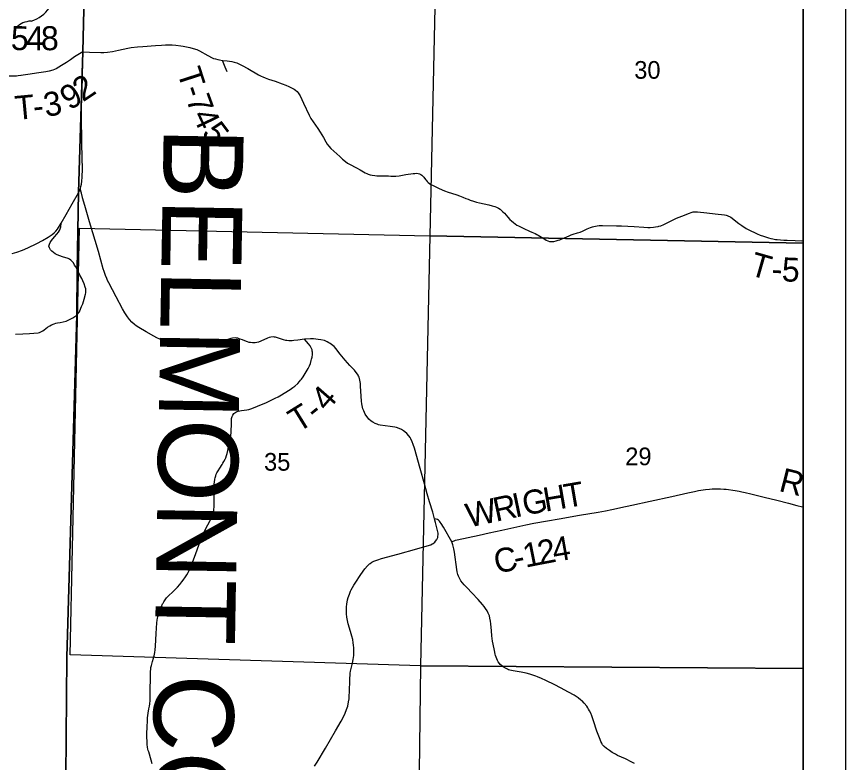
# Model space of a CAD drawing. Extents: x 0 to 34, y 0 to 22.
# Drawn here: x 7.038 to 9, y 17.164 to 18.929 of the extents above; entities that cross this region are included whole.
import ezdxf

# ---------------------------------------------------------------- set-up
doc = ezdxf.new("R2010")
doc.units = 0
for name, color, linetype in [('GM_X_Corporation', 7, 'Continuous'), ('GM_X_County_Road', 7, 'Continuous'), ('GM_X_County_Road_Text', 7, 'Continuous'), ('GM_X_County_Text', 7, 'Continuous'), ('GM_X_Section_Text', 7, 'Continuous'), ('GM_X_State_Route', 7, 'Continuous'), ('GM_X_State_Shield', 7, 'Continuous'), ('GM_X_Township_Road', 7, 'Continuous'), ('GM_X_Township_Road_Text', 7, 'Continuous'), ('GM_X_Township_Text', 7, 'Continuous'), ('SH_Data', 7, 'Continuous')]:
    doc.layers.add(name, color=color, linetype=linetype)

msp = doc.modelspace()

# ---------------------------------------------------------------- linework, layer by layer
at = {"layer": 'GM_X_Corporation'}
for points in [[(7.1227, 14.1), (8.9, 14.1), (8.9, 20.9), (7.231, 20.9), (7.2244, 20.2649), (7.1982, 19.2496), (7.1981, 19.2461), (7.1974, 19.2018), (7.1957, 19.0991), (7.1992, 18.9556), (7.197, 18.9465), (7.1949, 18.8464), (7.1846, 18.5133), (7.1817, 18.3306), (7.1804, 18.2238), (7.1572, 17.4131), (7.1504, 16.6562), (7.1434, 16.3848), (7.1318, 15.4937)], [(8.9, 18.393), (8.9, 19.2258), (8.0347, 19.2404), (8.0161, 18.4109)], [(8.0161, 18.4109), (7.9945, 17.3927), (7.1652, 17.4189), (7.1866, 18.4288)], [(8.9, 17.3865), (8.9, 18.393), (8.0161, 18.4109), (7.9945, 17.3927)], [(8.9, 16.3711), (8.9, 17.3865), (7.9945, 17.3927), (7.9815, 16.3875)]]:
    msp.add_lwpolyline(points, close=True, dxfattribs=at)
at = {"layer": 'GM_X_County_Road'}
for points in [[(8.068, 17.6868), (8.0768, 17.69), (8.0809, 17.6912), (8.133, 17.7023), (8.1569, 17.7076), (8.1864, 17.7138), (8.2435, 17.7264), (8.2626, 17.7302), (8.2947, 17.736), (8.3222, 17.7408), (8.3703, 17.7492), (8.4148, 17.7567), (8.4319, 17.7597), (8.4469, 17.7627), (8.4578, 17.765), (8.4687, 17.7674), (8.4943, 17.7732), (8.5376, 17.7827), (8.5892, 17.7935), (8.6269, 17.8022), (8.6427, 17.8058), (8.6524, 17.8077), (8.6633, 17.8094), (8.6684, 17.81), (8.6783, 17.8113), (8.6844, 17.8118), (8.6911, 17.8121), (8.7043, 17.812), (8.7122, 17.8114), (8.718, 17.8108), (8.7389, 17.8079), (8.7481, 17.8063), (8.7546, 17.8051), (8.7628, 17.8034), (8.7758, 17.8003), (8.8077, 17.7922), (8.8373, 17.7847), (8.8649, 17.7777), (8.8848, 17.7727), (8.8982, 17.7695), (8.9, 17.7691)], [(8.068, 17.6868), (8.0482, 17.7214), (8.0429, 17.7297), (8.041, 17.7328), (8.0388, 17.7355), (8.0368, 17.7374), (8.0342, 17.7392), (8.031, 17.7404), (8.0276, 17.741)], [(8.501, 17.1615), (8.4942, 17.1652), (8.4791, 17.1725), (8.4605, 17.1811), (8.458, 17.1824), (8.4554, 17.1838), (8.4482, 17.188), (8.4412, 17.1926), (8.4345, 17.1974), (8.4286, 17.2023), (8.4269, 17.2041), (8.4252, 17.2063), (8.4242, 17.2078), (8.423, 17.2098), (8.4211, 17.2139), (8.4194, 17.2185), (8.4119, 17.2382), (8.404, 17.2631), (8.3996, 17.2749), (8.3971, 17.281), (8.3944, 17.2867), (8.3921, 17.2907), (8.3904, 17.2934), (8.3877, 17.2973), (8.3817, 17.3049), (8.3765, 17.3098), (8.374, 17.312), (8.3676, 17.3169), (8.3577, 17.3233), (8.3447, 17.3308), (8.3259, 17.3409), (8.3118, 17.3482), (8.291, 17.3582), (8.2802, 17.3632), (8.2713, 17.3671), (8.2674, 17.3686), (8.2597, 17.3712), (8.2531, 17.3732), (8.2446, 17.3753), (8.2324, 17.3776), (8.2133, 17.381), (8.2097, 17.3817), (8.2057, 17.3827), (8.2026, 17.3838), (8.2, 17.3849), (8.1968, 17.3865), (8.1923, 17.389), (8.189, 17.3911), (8.185, 17.3942), (8.183, 17.3961), (8.1808, 17.3988), (8.1783, 17.4025), (8.1765, 17.4058), (8.1748, 17.4092), (8.1732, 17.4133), (8.1718, 17.4175), (8.171, 17.4204), (8.1691, 17.429), (8.166, 17.4441), (8.1649, 17.4514), (8.1633, 17.4641), (8.1621, 17.4756), (8.1606, 17.492), (8.1597, 17.4989), (8.1585, 17.5058), (8.1573, 17.5109), (8.1568, 17.5126), (8.1545, 17.5178), (8.1516, 17.5233), (8.1483, 17.5286), (8.1447, 17.5335), (8.1407, 17.5383), (8.1303, 17.5502), (8.127, 17.5536), (8.1194, 17.5618), (8.1006, 17.5813), (8.0975, 17.5847), (8.0936, 17.5894), (8.09, 17.5944), (8.0879, 17.5976), (8.0856, 17.6019), (8.0841, 17.6053), (8.0829, 17.6088), (8.0818, 17.6124), (8.0812, 17.6152), (8.0803, 17.6208), (8.0748, 17.6618), (8.0732, 17.67), (8.071, 17.6791), (8.0693, 17.6841), (8.068, 17.6868)]]:
    msp.add_lwpolyline(points, dxfattribs=at)
at = {"layer": 'GM_X_State_Route'}
for points in [[(7.1848, 18.5127), (7.1876, 18.5185), (7.189, 18.5224), (7.1902, 18.5276), (7.1914, 18.5332), (7.1923, 18.5399), (7.1932, 18.5491), (7.1935, 18.555), (7.1941, 18.5639), (7.1939, 18.5763), (7.1933, 18.5881), (7.1929, 18.6), (7.1927, 18.6262), (7.1926, 18.6491), (7.192, 18.6745), (7.1918, 18.6871), (7.192, 18.7145), (7.1935, 18.7555), (7.1941, 18.7873), (7.1949, 18.8249), (7.1951, 18.8459), (7.1953, 18.8628), (7.1956, 18.8765), (7.1961, 18.9023), (7.1966, 18.921), (7.1971, 18.9313)], [(7.7436, 17.1553), (7.7493, 17.165), (7.7691, 17.1984), (7.7812, 17.2189), (7.793, 17.2388), (7.806, 17.2619), (7.8108, 17.2708), (7.8157, 17.2809), (7.8191, 17.2894), (7.8219, 17.2977), (7.8239, 17.3075), (7.8249, 17.315), (7.8256, 17.3225), (7.8258, 17.3304), (7.826, 17.3364), (7.8265, 17.3548), (7.8268, 17.3638), (7.8273, 17.3711), (7.8279, 17.3759), (7.8287, 17.3801), (7.8332, 17.3994), (7.8349, 17.408), (7.8362, 17.4178), (7.8365, 17.4232), (7.8366, 17.4291), (7.8364, 17.4353), (7.8358, 17.4415), (7.835, 17.4477), (7.8336, 17.4549), (7.8317, 17.4628), (7.8282, 17.4746), (7.8233, 17.4925), (7.8214, 17.5002), (7.8199, 17.508), (7.819, 17.5159), (7.8186, 17.5242), (7.8188, 17.5316), (7.8197, 17.5394), (7.8204, 17.5437), (7.8216, 17.5491), (7.8233, 17.555), (7.8246, 17.559), (7.826, 17.5629), (7.8286, 17.5693), (7.8301, 17.5726), (7.8329, 17.5781), (7.8361, 17.5836), (7.8394, 17.5889), (7.8532, 17.6093), (7.8626, 17.6225), (7.8689, 17.6298), (7.8735, 17.6341), (7.8753, 17.6355), (7.8791, 17.638), (7.8835, 17.6403), (7.8883, 17.6425), (7.8933, 17.6442), (7.9018, 17.6467), (7.9403, 17.6573), (7.9851, 17.6697), (8.0157, 17.6788), (8.0184, 17.6797), (8.0217, 17.6813), (8.024, 17.6827), (8.0283, 17.686), (8.0322, 17.6908), (8.0331, 17.6923), (8.0343, 17.6949), (8.0349, 17.6967), (8.0355, 17.6994), (8.0359, 17.7039), (8.0358, 17.7069), (8.0353, 17.7104), (8.0297, 17.7318), (8.0276, 17.741), (8.023, 17.7565), (8.0158, 17.7811), (8.0103, 17.8), (8.0037, 17.8238), (7.9932, 17.8603), (7.9796, 17.9079), (7.9769, 17.9169), (7.9744, 17.9234), (7.9714, 17.9299), (7.9693, 17.9332), (7.9667, 17.9369), (7.9615, 17.9431), (7.9571, 17.9469), (7.9539, 17.9493), (7.9488, 17.9525), (7.9435, 17.955), (7.9376, 17.957), (7.9336, 17.958), (7.9225, 17.9597), (7.899, 17.9626), (7.8947, 17.9636), (7.8916, 17.9646), (7.8865, 17.9667), (7.8814, 17.9696), (7.8774, 17.9723), (7.8719, 17.977), (7.8677, 17.982), (7.865, 17.9858), (7.8632, 17.9888), (7.8613, 17.9924), (7.8597, 17.9961), (7.858, 18.0009), (7.8567, 18.0052), (7.8559, 18.0087), (7.8551, 18.0131), (7.8544, 18.0193), (7.8525, 18.0548), (7.8518, 18.0614), (7.8508, 18.0693), (7.8499, 18.0729), (7.8487, 18.0762), (7.8476, 18.0785), (7.8464, 18.0808), (7.8449, 18.0831), (7.8417, 18.0875), (7.8376, 18.0925), (7.8268, 18.1041), (7.8155, 18.1167), (7.8042, 18.1304), (7.7988, 18.1373), (7.7944, 18.1433), (7.7897, 18.1485), (7.7836, 18.1535), (7.7807, 18.1556), (7.7775, 18.1577), (7.7736, 18.1598), (7.7667, 18.1625), (7.7579, 18.1645), (7.7519, 18.1656), (7.7466, 18.1663), (7.7412, 18.1668), (7.7336, 18.1672), (7.7192, 18.1664), (7.704, 18.164), (7.6943, 18.1625), (7.6904, 18.1621), (7.6878, 18.162), (7.6825, 18.1621), (7.6778, 18.1627), (7.6752, 18.1631), (7.6699, 18.1644), (7.6558, 18.1695), (7.651, 18.1707), (7.6482, 18.1711), (7.6462, 18.1712), (7.6401, 18.1708), (7.6362, 18.1699), (7.6317, 18.1681), (7.616, 18.1612), (7.6107, 18.1593), (7.6064, 18.1582), (7.6031, 18.1577), (7.5997, 18.1574), (7.5963, 18.1573), (7.5915, 18.1579), (7.5885, 18.1585), (7.585, 18.1595), (7.5787, 18.1617), (7.5725, 18.1642), (7.5674, 18.1664), (7.5635, 18.1677), (7.5614, 18.1682), (7.5583, 18.1687), (7.5559, 18.1689), (7.5488, 18.1685), (7.5448, 18.1676), (7.5147, 18.1575), (7.511, 18.1564), (7.5054, 18.1547), (7.496, 18.1524), (7.4881, 18.1509), (7.4833, 18.1501), (7.476, 18.1491), (7.4625, 18.1479), (7.4542, 18.1477), (7.4447, 18.1479), (7.4374, 18.1484), (7.4312, 18.1491), (7.4245, 18.1503), (7.417, 18.1519), (7.4102, 18.1537), (7.4024, 18.156), (7.3949, 18.1585), (7.3847, 18.1625), (7.3773, 18.1657), (7.37, 18.1692), (7.3629, 18.1729), (7.3448, 18.1833), (7.3274, 18.1934), (7.3208, 18.1978), (7.3168, 18.201), (7.3111, 18.2061), (7.305, 18.2129), (7.3003, 18.2192), (7.294, 18.2285), (7.2886, 18.2379), (7.2736, 18.2662), (7.2563, 18.2992), (7.2534, 18.3052), (7.2513, 18.3098), (7.2485, 18.3167), (7.2452, 18.3258), (7.243, 18.3327), (7.2316, 18.3732), (7.2108, 18.4435), (7.1998, 18.4823), (7.1941, 18.5006), (7.194, 18.5009), (7.1913, 18.5113), (7.19, 18.5164), (7.189, 18.5224)], [(7.0274, 18.3686), (7.0386, 18.3719), (7.0524, 18.3768), (7.0645, 18.3818), (7.0863, 18.3926), (7.0997, 18.3997), (7.1124, 18.4072), (7.1223, 18.4141), (7.1268, 18.4176), (7.131, 18.4219), (7.1351, 18.4267), (7.1439, 18.4404), (7.1551, 18.4614), (7.1693, 18.4864), (7.1848, 18.5127)]]:
    msp.add_lwpolyline(points, dxfattribs=at)
at = {"layer": 'GM_X_State_Shield'}
for centre, major_axis, start_param, end_param in [((7.0392, 18.9835), (0.0874, 0), 5.101752, 6.440018), ((7.076, 18.8806), (0.0479, 0), 1.647645, 2.488434)]:
    msp.add_ellipse(centre, major_axis=major_axis, ratio=0.8, start_param=start_param, end_param=end_param, dxfattribs=at)
at = {"layer": 'GM_X_Township_Road'}
for points in [[(7.1951, 18.8459), (7.2106, 18.8456), (7.2373, 18.8442), (7.2449, 18.8442), (7.2535, 18.845), (7.2647, 18.8466), (7.2796, 18.8499), (7.3013, 18.8544), (7.3092, 18.8559), (7.3246, 18.8577), (7.3368, 18.8586), (7.3672, 18.8609), (7.3809, 18.862), (7.3908, 18.8628), (7.4003, 18.8629), (7.4063, 18.8625), (7.4148, 18.8616), (7.4269, 18.86), (7.4321, 18.8592), (7.44, 18.8578), (7.4479, 18.856), (7.4557, 18.8539), (7.4644, 18.8513), (7.4709, 18.8487), (7.4778, 18.8448), (7.484, 18.8414), (7.4998, 18.8324), (7.5043, 18.8306), (7.5088, 18.8291), (7.5145, 18.8276), (7.5187, 18.8268), (7.5254, 18.8259), (7.5365, 18.8245), (7.5472, 18.8229), (7.5534, 18.8216), (7.5593, 18.8197), (7.5657, 18.8169), (7.5724, 18.8136), (7.5853, 18.8063), (7.6107, 18.7917), (7.6169, 18.7884), (7.6208, 18.7865), (7.6266, 18.7842), (7.634, 18.7814), (7.6498, 18.7763), (7.6669, 18.7706), (7.6753, 18.7671), (7.6826, 18.7639), (7.6905, 18.7602), (7.6948, 18.7578), (7.6984, 18.7553), (7.7019, 18.7522), (7.7047, 18.7491), (7.7064, 18.7466), (7.709, 18.7421), (7.7171, 18.7249), (7.7304, 18.6965), (7.7321, 18.693), (7.7347, 18.6882), (7.7399, 18.6807), (7.751, 18.6648), (7.7566, 18.6558), (7.7642, 18.6431), (7.7699, 18.6331), (7.7731, 18.6279), (7.7768, 18.6226), (7.7818, 18.6171), (7.8029, 18.5981), (7.8098, 18.5919), (7.8165, 18.5863), (7.8212, 18.5828), (7.8261, 18.5799), (7.8426, 18.5713), (7.8511, 18.5668), (7.8632, 18.5598), (7.8669, 18.5579), (7.8703, 18.5566), (7.8751, 18.5553), (7.88, 18.5541), (7.8859, 18.5532), (7.891, 18.5528), (7.8951, 18.5527), (7.9031, 18.5525), (7.9119, 18.5528), (7.9185, 18.5526), (7.924, 18.552), (7.9288, 18.5515), (7.9324, 18.5514), (7.9358, 18.5517), (7.9433, 18.5527), (7.9597, 18.5555), (7.9765, 18.5577), (7.9809, 18.5582), (7.9857, 18.5585), (7.9883, 18.5582), (7.9914, 18.5573), (7.9946, 18.5561), (7.9972, 18.5545), (7.9999, 18.552), (8.002, 18.5492), (8.0058, 18.544), (8.0074, 18.542), (8.0102, 18.5389), (8.0125, 18.5368), (8.0154, 18.5344), (8.0184, 18.5323), (8.0224, 18.5301), (8.0286, 18.5271), (8.0387, 18.5225), (8.0511, 18.5174), (8.0598, 18.5141), (8.0676, 18.5116), (8.0802, 18.5074), (8.0867, 18.5049), (8.0945, 18.502), (8.1018, 18.499), (8.1066, 18.497), (8.1118, 18.495), (8.1197, 18.4924), (8.1265, 18.4904), (8.1337, 18.4886), (8.145, 18.486), (8.1556, 18.4837), (8.1641, 18.4817), (8.1701, 18.48), (8.1741, 18.4785), (8.1788, 18.4761), (8.1829, 18.4734), (8.1861, 18.4704), (8.1892, 18.4672), (8.1927, 18.4639), (8.2011, 18.4545), (8.2055, 18.4496), (8.2096, 18.4458), (8.2146, 18.4419), (8.2185, 18.439), (8.2225, 18.4361), (8.2259, 18.4342), (8.2321, 18.431), (8.2386, 18.4276), (8.2432, 18.4256), (8.2474, 18.4238), (8.2524, 18.4217), (8.2577, 18.4196), (8.2619, 18.4178), (8.2655, 18.4161), (8.2692, 18.414), (8.2727, 18.4119), (8.2765, 18.4095), (8.2802, 18.4071), (8.2842, 18.4048), (8.2883, 18.4024), (8.292, 18.4006), (8.2955, 18.3988), (8.2995, 18.3975), (8.3033, 18.397), (8.3097, 18.3975), (8.3149, 18.3987), (8.32, 18.4001), (8.3238, 18.4012), (8.3274, 18.4026), (8.3309, 18.4039), (8.3351, 18.4056), (8.3461, 18.4108), (8.3507, 18.4128), (8.3555, 18.4146), (8.3655, 18.4176), (8.3718, 18.4194), (8.3775, 18.4216), (8.3889, 18.4269), (8.3965, 18.4302), (8.401, 18.4317), (8.4043, 18.4327), (8.4082, 18.4336), (8.412, 18.4342), (8.4172, 18.4347), (8.4251, 18.4349), (8.458, 18.4343), (8.47, 18.4341), (8.4997, 18.4326), (8.5231, 18.4308), (8.5321, 18.4305), (8.538, 18.4306), (8.5454, 18.4311), (8.5502, 18.4317), (8.5565, 18.4328), (8.5587, 18.4333), (8.5627, 18.4346), (8.5704, 18.4376), (8.5746, 18.4396), (8.5982, 18.4513), (8.6005, 18.4524), (8.6124, 18.4571), (8.6312, 18.4644), (8.6347, 18.4657), (8.6397, 18.467), (8.6434, 18.4674), (8.6475, 18.4672)], [(7.0538, 18.7907), (7.0492, 18.7901), (7.0477, 18.79), (7.0418, 18.7893), (7.0382, 18.7882), (7.0281, 18.7881), (7.0164, 18.7882), (6.9853, 18.769), (6.966, 18.7665), (6.9512, 18.7689), (6.939, 18.7774), (6.9354, 18.7868), (6.9404, 18.7998), (6.9361, 18.8087), (6.9363, 18.8145), (6.9361, 18.8207), (6.9344, 18.8302), (6.9331, 18.8358), (6.9329, 18.8366)], [(7.1951, 18.8459), (7.1748, 18.834), (7.1657, 18.8273), (7.1558, 18.8204), (7.1445, 18.8133), (7.1318, 18.8059), (7.1237, 18.8023), (7.1152, 18.7999), (7.1073, 18.7983), (7.0909, 18.7963), (7.0644, 18.792), (7.0538, 18.7907)], [(7.5364, 18.7988), (7.5315, 18.8098), (7.5254, 18.8259)], [(8.6475, 18.4672), (8.6496, 18.4671), (8.6722, 18.4649), (8.6915, 18.463), (8.7141, 18.4602), (8.7174, 18.4595), (8.7202, 18.4587), (8.7234, 18.4574), (8.7253, 18.4565), (8.7269, 18.4556), (8.729, 18.4544), (8.7474, 18.4401), (8.755, 18.4347), (8.7654, 18.4282), (8.7763, 18.4221), (8.7846, 18.4181), (8.7914, 18.415), (8.7985, 18.4121), (8.8057, 18.4094), (8.8182, 18.4055), (8.8232, 18.4042), (8.8282, 18.4031), (8.8343, 18.4022), (8.8382, 18.4018), (8.8542, 18.4005), (8.862, 18.4001), (8.8808, 18.3994), (8.8959, 18.399), (8.9, 18.3995)], [(7.1819, 18.33), (7.1779, 18.3371), (7.1755, 18.3413), (7.1724, 18.3465), (7.1694, 18.35), (7.1663, 18.3529), (7.1633, 18.355), (7.1599, 18.3566), (7.1468, 18.3607), (7.1402, 18.3631), (7.1337, 18.366), (7.1295, 18.3683), (7.1251, 18.3711), (7.1215, 18.3741), (7.1181, 18.3778), (7.1156, 18.382), (7.1146, 18.3861), (7.115, 18.3884), (7.1156, 18.3911), (7.1175, 18.3949), (7.1208, 18.3996), (7.1274, 18.4082), (7.1332, 18.4147), (7.1371, 18.4192), (7.1397, 18.423), (7.1411, 18.4268), (7.1424, 18.4317), (7.1439, 18.4404)], [(7.1806, 18.2232), (7.1821, 18.2248), (7.1852, 18.2288), (7.1866, 18.2309), (7.1877, 18.2329), (7.192, 18.2431), (7.1945, 18.2496), (7.198, 18.2607), (7.2015, 18.2726), (7.2022, 18.2756), (7.2023, 18.2774), (7.2018, 18.2852), (7.2006, 18.2893), (7.1977, 18.2967), (7.1948, 18.3038), (7.1921, 18.3096), (7.188, 18.3177), (7.1819, 18.33)], [(7.0354, 18.1778), (7.053, 18.179), (7.0688, 18.1798), (7.0792, 18.1803), (7.0894, 18.1814), (7.0923, 18.1822), (7.0953, 18.1833), (7.1, 18.1859), (7.1036, 18.1882), (7.1114, 18.1941), (7.1168, 18.1975), (7.121, 18.1998), (7.1266, 18.2023), (7.1309, 18.2036), (7.1351, 18.2043), (7.1412, 18.2052), (7.1485, 18.2067), (7.1556, 18.2089), (7.1635, 18.2124), (7.1708, 18.2166), (7.1806, 18.2232)], [(7.3591, 17.161), (7.3568, 17.1698), (7.3508, 17.1893), (7.3497, 17.1928), (7.3489, 17.1959), (7.3481, 17.2004), (7.3473, 17.2069), (7.3468, 17.2149), (7.3464, 17.2236), (7.3466, 17.2337), (7.3471, 17.2472), (7.3476, 17.264), (7.3479, 17.27), (7.3484, 17.2754), (7.3492, 17.2813), (7.3512, 17.2911), (7.3526, 17.2976), (7.3533, 17.3032), (7.3539, 17.3108), (7.3543, 17.3178), (7.3545, 17.3267), (7.3548, 17.373), (7.3551, 17.3798), (7.3556, 17.385), (7.3561, 17.3893), (7.3571, 17.3938), (7.3595, 17.4031), (7.3622, 17.4112), (7.3636, 17.4168), (7.3652, 17.4244), (7.3663, 17.4308), (7.367, 17.4392), (7.3685, 17.4695), (7.3704, 17.4944), (7.3711, 17.5009), (7.3718, 17.5055), (7.3727, 17.5092), (7.3738, 17.5135), (7.3751, 17.5177), (7.3785, 17.5267), (7.3838, 17.5393), (7.3848, 17.5414), (7.3865, 17.5443), (7.3896, 17.5491), (7.3931, 17.5536), (7.3969, 17.5577), (7.409, 17.5691), (7.4186, 17.5793), (7.4242, 17.5857), (7.4291, 17.5917), (7.4323, 17.596), (7.4379, 17.6037), (7.4411, 17.6085), (7.4444, 17.614), (7.4468, 17.6189), (7.4498, 17.6255), (7.4556, 17.6401), (7.4617, 17.6565), (7.4703, 17.6806), (7.4743, 17.6925), (7.4779, 17.7016), (7.4804, 17.7072), (7.4835, 17.7136), (7.4908, 17.7266), (7.4962, 17.7366), (7.4987, 17.7416), (7.5004, 17.7457), (7.5023, 17.7513), (7.5035, 17.7557), (7.5047, 17.7604), (7.5052, 17.7639), (7.5056, 17.7684), (7.5057, 17.7732), (7.5054, 17.7964), (7.5058, 17.8235), (7.5063, 17.8278), (7.5074, 17.8347), (7.5082, 17.838), (7.5094, 17.8426), (7.5108, 17.8464), (7.5123, 17.8496), (7.5149, 17.8547), (7.5191, 17.8611), (7.5249, 17.8696), (7.5265, 17.8724), (7.5289, 17.8766), (7.5314, 17.8817), (7.533, 17.8853), (7.5349, 17.8904), (7.5366, 17.8957), (7.5381, 17.9023), (7.542, 17.9221), (7.5449, 17.9382), (7.5456, 17.9451), (7.5462, 17.9539), (7.5464, 17.9597), (7.5468, 17.9781), (7.5473, 17.9805), (7.5482, 17.983), (7.5497, 17.9858), (7.5526, 17.9899), (7.5548, 17.9918), (7.5567, 17.9929), (7.5587, 17.994), (7.5604, 17.9947), (7.5628, 17.9955), (7.5708, 17.997), (7.5828, 17.9988), (7.5876, 17.9999), (7.5923, 18.0012), (7.5989, 18.0034), (7.6083, 18.0072), (7.6293, 18.0163), (7.6405, 18.0214), (7.6501, 18.0262), (7.6569, 18.0298), (7.6649, 18.0344), (7.6813, 18.0442), (7.686, 18.0473), (7.692, 18.0516), (7.6963, 18.055), (7.7036, 18.0615), (7.7078, 18.0661), (7.71, 18.0687), (7.7123, 18.0717), (7.7161, 18.077), (7.7211, 18.0849), (7.7281, 18.0967), (7.7311, 18.1026), (7.7337, 18.1088), (7.7357, 18.1153), (7.7365, 18.1185), (7.7375, 18.1233), (7.7384, 18.1297), (7.7386, 18.1318), (7.7384, 18.1349), (7.738, 18.138), (7.7375, 18.1405), (7.7368, 18.1426), (7.7349, 18.1469), (7.7329, 18.1502), (7.7294, 18.1547), (7.7192, 18.1664)]]:
    msp.add_lwpolyline(points, dxfattribs=at)
at = {"layer": 'GM_X_Township_Text'}
for points in [[(7.1227, 14.1), (8.9, 14.1), (8.9, 19.2243), (7.7835, 19.2432), (7.6914, 19.2442), (7.3421, 19.2478), (7.2323, 19.2489), (7.1982, 19.2496)], [(7.1227, 14.1), (7.1318, 15.4937), (7.1434, 16.3848), (7.1504, 16.6562), (7.1572, 17.4131), (7.1804, 18.2238), (7.1817, 18.3306), (7.1846, 18.5133), (7.1949, 18.8464), (7.197, 18.9465), (7.1992, 18.9556), (7.1957, 19.0991), (7.1536, 19.0995)]]:
    msp.add_lwpolyline(points, dxfattribs=at)
at = {"layer": 'SH_Data'}
for p, q in [((9, 21), (9, 14)), ((8.9, 20.9), (8.9, 14.1))]:
    msp.add_line(p, q, dxfattribs=at)

# ---------------------------------------------------------------- texts
at = {"layer": 'GM_X_County_Road_Text'}
for s, rotation, p in [('R', 345.9212, (8.8403, 17.8072)), ('H', 9.8067, (8.2896, 17.7576)), ('T', 9.7195, (8.3389, 17.7661)), ('R', 12.1351, (8.1726, 17.7338)), ('I', 11.7769, (8.2182, 17.7436)), ('G', 10.7734, (8.2407, 17.7483)), ('W', 12.1591, (8.1083, 17.7199)), ('4', 9.9371, (8.311, 17.6384)), ('1', 11.3936, (8.2426, 17.6251)), ('2', 10.7629, (8.2768, 17.6319)), ('C', 11.959, (8.1743, 17.6106)), ('-', 11.7998, (8.2199, 17.6203))]:
    msp.add_text(s, height=0.0568, rotation=rotation, dxfattribs=at).set_placement(p)
at = {"layer": 'GM_X_County_Text'}
msp.add_text('BELMONT COUNTY', height=0.189394, rotation=269.0214, dxfattribs=at).set_placement((7.3864, 18.6686))
at = {"layer": 'GM_X_Section_Text'}
for s, p in [('30', (8.5001, 18.7823)), ('35', (7.6238, 17.8548)), ('29', (8.4788, 17.8677))]:
    msp.add_text(s, height=0.04186, rotation=0, dxfattribs=at).set_placement(p)
at = {"layer": 'GM_X_Township_Road_Text'}
for s, rotation, p in [('5', 358.6139, (7.0239, 18.8506)), ('4', 0.006, (7.0604, 18.8497)), ('8', 0.3588, (7.0958, 18.8497)), ('T', 287.8807, (7.4174, 18.7987)), ('2', 34.0159, (7.1951, 18.726)), ('9', 31.9773, (7.1636, 18.7063)), ('-', 288.3175, (7.4306, 18.7578)), ('T', 5.3473, (7.0366, 18.6846)), ('3', 10.2183, (7.1073, 18.6916)), ('7', 290.0325, (7.4386, 18.7339)), ('-', 5.7996, (7.0794, 18.6886)), ('4', 295.6491, (7.4529, 18.6954)), ('5', 306.773, (7.4743, 18.6536)), ('T', 344.0364, (8.7702, 18.3185)), ('5', 357.5471, (8.8485, 18.3031)), ('-', 356.4484, (8.8241, 18.3046)), ('4', 48.7838, (7.7724, 17.9928)), ('T', 31.7333, (7.7041, 17.9438)), ('-', 39.033, (7.7467, 17.9708))]:
    msp.add_text(s, height=0.0568, rotation=rotation, dxfattribs=at).set_placement(p)

doc.saveas('drawing.dxf')
